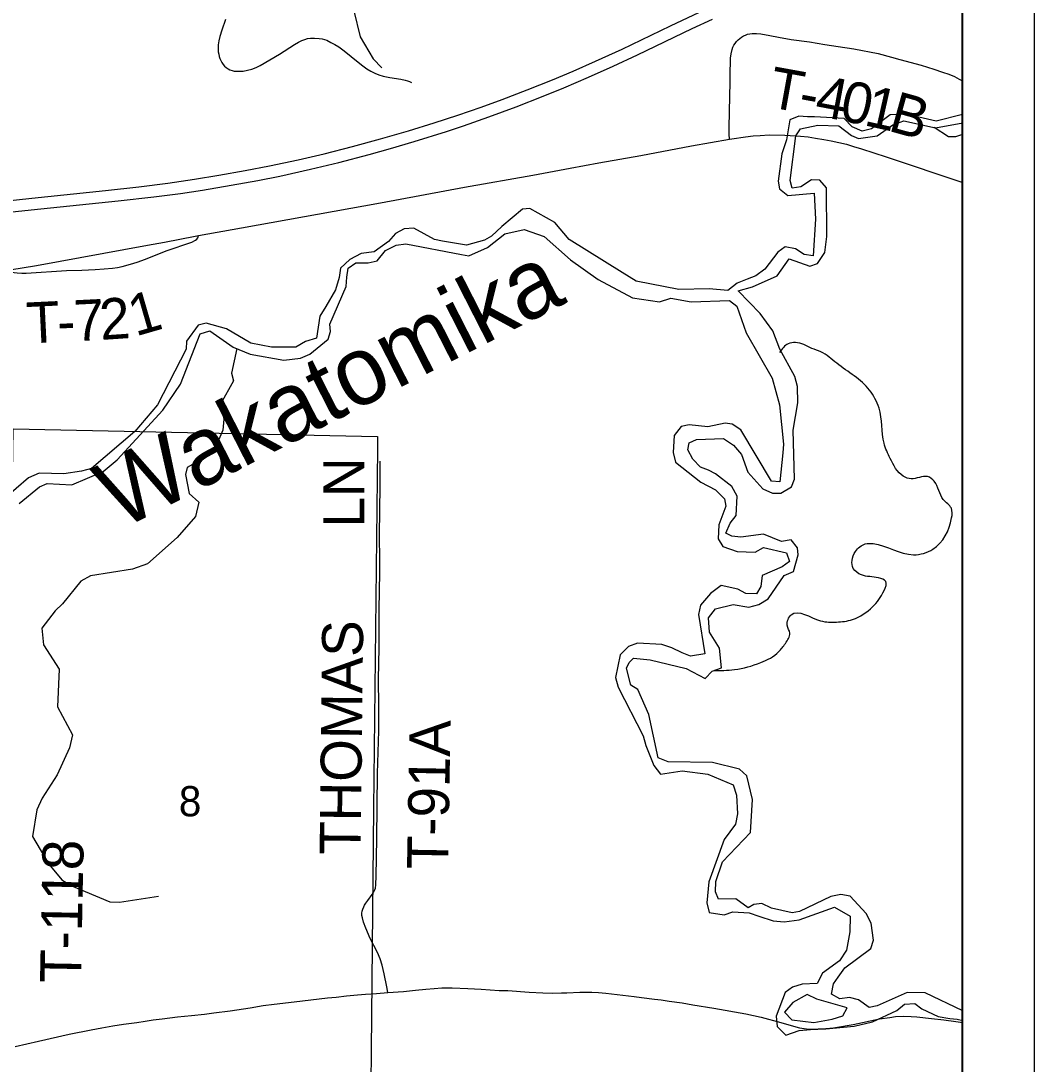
# Model space of a CAD drawing. Extents: x 0 to 34, y 0 to 22.
# Drawn here: x 8.096 to 9.5, y 19.303 to 20.748 of the extents above; entities that cross this region are included whole.
import ezdxf

# ---------------------------------------------------------------- set-up
doc = ezdxf.new("R2010")
doc.units = 0
for name, color, linetype in [('GM_X_County', 7, 'Continuous'), ('GM_X_County_Road', 7, 'Continuous'), ('GM_X_Minor_River', 7, 'Continuous'), ('GM_X_Minor_River_Text', 7, 'Continuous'), ('GM_X_Section', 7, 'Continuous'), ('GM_X_Section_Text', 7, 'Continuous'), ('GM_X_State_Route', 7, 'Continuous'), ('GM_X_Township', 7, 'Continuous'), ('GM_X_Township_Road', 7, 'Continuous'), ('GM_X_Township_Road_Text', 7, 'Continuous'), ('SH_Data', 7, 'Continuous')]:
    doc.layers.add(name, color=color, linetype=linetype)

msp = doc.modelspace()

# ---------------------------------------------------------------- linework, layer by layer
at = {"layer": 'GM_X_County'}
msp.add_lwpolyline([(7.0736, 21.2003), (2.6013, 21.2003), (2.6013, 14.4003), (9.4013, 14.4003), (9.4013, 21.1598)], dxfattribs=at)
at = {"layer": 'GM_X_County_Road'}
for points in [[(8.3426, 20.4502), (8.402, 20.4611), (8.5947, 20.4955), (8.7107, 20.5171), (8.8055, 20.5338), (8.8575, 20.5435), (8.8971, 20.5509), (8.9552, 20.5614), (9.0255, 20.5744), (9.0778, 20.5836)], [(9.0778, 20.5836), (9.0812, 20.5842), (9.1, 20.587), (9.1107, 20.5884), (9.1203, 20.589), (9.1328, 20.5896), (9.1545, 20.5894), (9.1762, 20.5881), (9.1872, 20.5868), (9.1973, 20.5854), (9.2085, 20.5835), (9.219, 20.5817), (9.2401, 20.5768), (9.2499, 20.5737), (9.2607, 20.5705), (9.295, 20.5593), (9.4013, 20.5238)], [(8.2717, 20.437), (8.2951, 20.4413), (8.3379, 20.4493), (8.3426, 20.4502)], [(8.0813, 20.4027), (8.1179, 20.4089), (8.2717, 20.437)], [(8.6046, 19.4017), (8.6266, 19.4034), (8.6432, 19.4049), (8.6574, 19.4063), (8.669, 19.4076), (8.6793, 19.4084), (8.6939, 19.4085), (8.7155, 19.4074), (8.7341, 19.4063), (8.7587, 19.4048), (8.7708, 19.4044), (8.8006, 19.4023), (8.8192, 19.4014), (8.8329, 19.4011), (8.8452, 19.4014), (8.8527, 19.4014), (8.8708, 19.4023), (8.8872, 19.4023), (8.8965, 19.402), (8.9067, 19.401), (8.946, 19.3962), (8.9559, 19.3949), (8.9741, 19.3926), (8.9832, 19.3915), (8.9945, 19.3899), (9.0123, 19.3874), (9.0274, 19.3847), (9.0561, 19.3801), (9.1006, 19.3724), (9.1218, 19.3675), (9.1489, 19.3601), (9.1698, 19.3544), (9.1751, 19.3531), (9.1784, 19.3524), (9.1845, 19.3517), (9.1942, 19.3512), (9.2003, 19.3512), (9.2065, 19.3514), (9.2219, 19.353), (9.2494, 19.3577), (9.2858, 19.3653), (9.3002, 19.3674), (9.3078, 19.3684), (9.3192, 19.3693), (9.3296, 19.3687), (9.3376, 19.368), (9.3579, 19.366), (9.3749, 19.3639), (9.3916, 19.3617), (9.4013, 19.3603)], [(8.0885, 19.3272), (8.1209, 19.3346), (8.1634, 19.344), (8.1938, 19.35), (8.2087, 19.3528), (8.2236, 19.3556), (8.2386, 19.358), (8.2568, 19.3604), (8.2686, 19.3622), (8.2794, 19.3641), (8.2919, 19.3656), (8.3134, 19.368), (8.3326, 19.3698), (8.3506, 19.3718), (8.3638, 19.3735), (8.3864, 19.3765), (8.414, 19.3808), (8.4322, 19.3837), (8.4474, 19.3858), (8.4751, 19.389), (8.5209, 19.3943), (8.5331, 19.3956), (8.5473, 19.3971), (8.5625, 19.3984), (8.5738, 19.3994), (8.5892, 19.4003), (8.6046, 19.4017)]]:
    msp.add_lwpolyline(points, dxfattribs=at)
at = {"layer": 'GM_X_Minor_River'}
for points in [[(8.4113, 21.1729), (8.4074, 21.1403), (8.3955, 21.1084), (8.397, 21.0936), (8.4138, 21.0694), (8.4237, 21.046), (8.4228, 21.0099), (8.4233, 20.9773), (8.4287, 20.9473), (8.4631, 20.8811), (8.4939, 20.8353), (8.5133, 20.8077), (8.5517, 20.7718), (8.5578, 20.7616), (8.5663, 20.7255), (8.5842, 20.6949), (8.5964, 20.6828)], [(9.2479, 20.6009), (9.2368, 20.6126), (9.1959, 20.6147), (9.1861, 20.6147), (9.174, 20.6158), (9.1615, 20.6104), (9.1571, 20.5827), (9.1507, 20.5637), (9.1456, 20.5254), (9.1472, 20.5152), (9.1586, 20.5057), (9.1953, 20.5088), (9.1972, 20.473), (9.1941, 20.4224), (9.1816, 20.4239), (9.1695, 20.4318), (9.1551, 20.4348), (9.1449, 20.4275), (9.1268, 20.4036), (9.1144, 20.3944), (9.1023, 20.3898), (9.0887, 20.3845), (9.0755, 20.3742), (9.0497, 20.3767), (9.0077, 20.3754), (8.9486, 20.387), (8.9292, 20.3991), (8.856, 20.4447), (8.8362, 20.4682), (8.8013, 20.4878), (8.7911, 20.487), (8.7624, 20.463), (8.7484, 20.4493), (8.7386, 20.4439), (8.7139, 20.4372), (8.6803, 20.4426), (8.6694, 20.4448), (8.6405, 20.4603), (8.6273, 20.4595), (8.6152, 20.453), (8.6054, 20.4419), (8.5857, 20.4278), (8.5676, 20.4255), (8.5521, 20.4171), (8.5393, 20.4053), (8.5371, 20.392), (8.532, 20.375), (8.5187, 20.3521), (8.5104, 20.3388), (8.5057, 20.3081), (8.4906, 20.3034), (8.4774, 20.2959), (8.4435, 20.2959), (8.4148, 20.3013), (8.3814, 20.3212), (8.353, 20.3291), (8.3421, 20.326), (8.3259, 20.304), (8.3252, 20.293), (8.2857, 20.2158), (8.2541, 20.1789), (8.1941, 20.1278), (8.1802, 20.124), (8.156, 20.1201), (8.1219, 20.1211), (8.1071, 20.1146), (8.0728, 20.0853)], [(9.0539, 19.8471), (9.0671, 19.8517), (9.0643, 19.8787), (9.0502, 19.901), (9.049, 19.9207), (9.0588, 19.9333), (9.083, 19.9391), (9.1046, 19.9357), (9.1186, 19.9392), (9.1314, 19.9472), (9.1536, 19.9795), (9.1668, 19.9852), (9.1732, 20.008), (9.172, 20.0179), (9.1636, 20.0289), (9.15, 20.0265), (9.1249, 20.0366), (9.0938, 20.0324), (9.0812, 20.0338), (9.0731, 20.038), (9.0787, 20.0521), (9.0874, 20.0627), (9.0888, 20.0893), (9.0812, 20.1026), (9.0588, 20.1203), (9.0489, 20.1252), (9.0379, 20.1293), (9.0272, 20.1407), (9.0204, 20.1536), (9.0219, 20.1631), (9.0321, 20.168), (9.0699, 20.1693), (9.0836, 20.1599), (9.0946, 20.147), (9.1034, 20.1227), (9.124, 20.0997), (9.1376, 20.0933), (9.149, 20.0937), (9.1637, 20.1021), (9.1682, 20.1127), (9.166, 20.1806), (9.1727, 20.2186), (9.1722, 20.241), (9.1687, 20.255), (9.1477, 20.2929), (9.1378, 20.3182), (9.1203, 20.3425), (9.0898, 20.3738), (9.1099, 20.3792), (9.1439, 20.3945), (9.1608, 20.4181), (9.1893, 20.4079), (9.1998, 20.4114), (9.21, 20.427), (9.2129, 20.449), (9.2123, 20.5165), (9.2031, 20.5271), (9.1914, 20.5275), (9.177, 20.5179), (9.1646, 20.516), (9.1619, 20.5266), (9.1699, 20.5885), (9.1763, 20.598), (9.2005, 20.603), (9.2293, 20.6023), (9.2468, 20.5891), (9.2566, 20.5846), (9.2827, 20.5885), (9.3042, 20.6037), (9.3194, 20.6091), (9.3633, 20.5997), (9.4013, 20.6062)], [(9.4013, 20.6184), (9.4007, 20.6181), (9.3644, 20.6085), (9.3224, 20.6186), (9.3004, 20.6174), (9.2747, 20.5983), (9.2619, 20.5948), (9.2479, 20.6009)], [(9.3613, 20.6002), (9.3815, 20.5877), (9.3914, 20.5873), (9.4013, 20.5906)], [(8.0941, 20.0793), (8.122, 20.1022), (8.1329, 20.1068), (8.167, 20.105), (8.2104, 20.1234), (8.2297, 20.1397), (8.293, 20.2086), (8.3174, 20.2444), (8.3448, 20.3143), (8.358, 20.3185), (8.3903, 20.2959), (8.4141, 20.2861), (8.4607, 20.2775), (8.4838, 20.2803), (8.4967, 20.286), (8.5219, 20.3066), (8.5253, 20.3176), (8.5245, 20.3275), (8.547, 20.3795), (8.5481, 20.3928), (8.5499, 20.4053), (8.5603, 20.4127), (8.5773, 20.4127), (8.59, 20.4153), (8.6013, 20.4298), (8.6164, 20.437), (8.6296, 20.4386), (8.7069, 20.4241), (8.7168, 20.4222), (8.7428, 20.4337), (8.767, 20.4527), (8.7935, 20.4585), (8.8211, 20.4488), (8.8576, 20.4167), (8.896, 20.3895), (8.9434, 20.3638), (8.9809, 20.3587), (8.9968, 20.3636), (9.0248, 20.3584), (9.0778, 20.3605), (9.088, 20.3526), (9.1011, 20.3155), (9.1369, 20.2526), (9.1473, 20.2158), (9.1528, 20.1612), (9.1518, 20.1495), (9.1478, 20.1092), (9.136, 20.11), (9.0937, 20.1811), (9.0816, 20.1891), (9.0721, 20.1905), (9.0479, 20.1855), (9.0221, 20.1881), (9.0112, 20.1858), (9.0014, 20.1732), (9, 20.1497), (9.003, 20.1364), (9.0384, 20.1085), (9.0585, 20.0983), (9.071, 20.0855), (9.073, 20.0756), (9.0632, 20.0494), (9.0622, 20.03), (9.0687, 20.0194), (9.0887, 20.0127), (9.1134, 20.0116), (9.1251, 20.0181), (9.1569, 20.011), (9.1611, 19.9989), (9.1509, 19.9913), (9.1233, 19.9794), (9.1215, 19.9642), (9.1155, 19.954), (9.1004, 19.9547), (9.0897, 19.9603), (9.0666, 19.9656), (9.0519, 19.9545), (9.038, 19.9385), (9.035, 19.9252)], [(8.3955, 20.2937), (8.3881, 20.2596), (8.3908, 20.249), (8.3731, 20.2166), (8.3774, 20.1962), (8.3763, 20.1806), (8.3666, 20.1582), (8.3439, 20.1387), (8.3269, 20.1288), (8.3243, 20.1193), (8.3293, 20.0928), (8.343, 20.0811), (8.3382, 20.0613), (8.3129, 20.032), (8.2718, 19.9954), (8.251, 19.9881), (8.1927, 19.9791), (8.1794, 19.9718), (8.1542, 19.9402), (8.144, 19.9307), (8.1255, 19.9063), (8.1279, 19.8836), (8.1493, 19.8495), (8.1473, 19.7975), (8.1679, 19.7589), (8.1638, 19.7407), (8.1466, 19.7035), (8.1259, 19.6711), (8.1187, 19.6548), (8.1125, 19.618), (8.135, 19.5797), (8.1533, 19.5578), (8.1658, 19.5499), (8.2194, 19.5274), (8.233, 19.5271), (8.2868, 19.5353)], [(9.035, 19.9252), (9.0436, 19.871), (9.0239, 19.8679), (9.0125, 19.8724), (8.9981, 19.8792), (8.9844, 19.8837), (8.9504, 19.8859), (8.9379, 19.8809), (8.9266, 19.8695), (8.9203, 19.8383), (8.9238, 19.8247), (8.9585, 19.7573), (8.9623, 19.744), (8.9734, 19.7164), (8.9822, 19.7042), (9.0124, 19.7089), (9.0481, 19.7041), (9.0833, 19.6894), (9.0879, 19.6754), (9.0892, 19.6492), (9.0862, 19.6348), (9.0708, 19.6139), (9.0495, 19.555), (9.0465, 19.5262), (9.05, 19.5125), (9.0705, 19.5096), (9.0826, 19.5138), (9.1053, 19.5123), (9.1186, 19.5074), (9.1383, 19.5011), (9.1538, 19.4996), (9.1746, 19.5027), (9.2234, 19.5199), (9.245, 19.5075), (9.2447, 19.4859), (9.2399, 19.4604), (9.2305, 19.4456), (9.2067, 19.4288), (9.1996, 19.4144), (9.1788, 19.4136), (9.1652, 19.4093), (9.155, 19.4017), (9.1426, 19.3691), (9.1442, 19.3546), (9.156, 19.3429), (9.1745, 19.3491), (9.201, 19.3514), (9.2116, 19.3515), (9.2509, 19.3554), (9.2763, 19.3612), (9.3099, 19.3768), (9.3205, 19.3856), (9.3348, 19.3868), (9.3443, 19.3792), (9.3671, 19.3687), (9.383, 19.3657), (9.3932, 19.365), (9.4013, 19.3633)], [(9.4013, 19.3763), (9.3492, 19.4012), (9.3242, 19.4019), (9.2826, 19.3832), (9.2713, 19.3813), (9.2568, 19.3918), (9.2443, 19.3948), (9.2307, 19.3933), (9.2193, 19.3997), (9.2219, 19.4137), (9.2283, 19.4232), (9.2377, 19.4361), (9.274, 19.4628), (9.2777, 19.4742), (9.2742, 19.4977), (9.2673, 19.5114), (9.2452, 19.5352), (9.2324, 19.5374), (9.2184, 19.5347), (9.1749, 19.5141), (9.1647, 19.5122), (9.1363, 19.5185), (9.1226, 19.5249), (9.1117, 19.5237), (9.1037, 19.5191), (9.0867, 19.5318), (9.0628, 19.5312), (9.0586, 19.5414), (9.0589, 19.5558), (9.0683, 19.5828), (9.1071, 19.6235), (9.1099, 19.669), (9.1022, 19.702), (9.0919, 19.7111), (9.0544, 19.7204), (8.9931, 19.7214), (8.9794, 19.727), (8.9663, 19.7869), (8.951, 19.8217), (8.9415, 19.8274), (8.9352, 19.8513), (8.939, 19.8588), (8.9448, 19.865), (8.9679, 19.8624), (9.0179, 19.8508), (9.0441, 19.8369), (9.0539, 19.8471)], [(9.1989, 19.3924), (9.1856, 19.3992), (9.1656, 19.3881), (9.1543, 19.3748), (9.1642, 19.3642), (9.1949, 19.3605), (9.2202, 19.3648)], [(9.2202, 19.3648), (9.235, 19.3694), (9.241, 19.3804), (9.1989, 19.3924)]]:
    msp.add_lwpolyline(points, dxfattribs=at)
for points in [[(9.0552, 19.8476), (9.0849, 19.8491), (9.1212, 19.8588), (9.1461, 19.8736), (9.1555, 19.8854), (9.1615, 19.8995), (9.1581, 19.9105), (9.1633, 19.9249), (9.2042, 19.9167), (9.2262, 19.9149), (9.2485, 19.9184), (9.2761, 19.9359), (9.2923, 19.9587), (9.2945, 19.9713), (9.2846, 19.9762), (9.2607, 19.9803), (9.2494, 19.9893), (9.2478, 20.0003), (9.2527, 20.0129), (9.2659, 20.0231), (9.2768, 20.0236), (9.3329, 20.0082), (9.3598, 20.0159), (9.3857, 20.0592), (9.3853, 20.0725), (9.3742, 20.0846), (9.3616, 20.11), (9.3522, 20.1164), (9.3295, 20.1133), (9.3188, 20.117), (9.3006, 20.1416), (9.2921, 20.1625), (9.2851, 20.2114), (9.2794, 20.2246), (9.2721, 20.236), (9.2266, 20.2734), (9.2045, 20.2893), (9.192, 20.2938)], [(9.192, 20.2938), (9.1693, 20.302), (9.1594, 20.3005), (9.1474, 20.2883)]]:
    msp.add_spline(points, degree=3, dxfattribs=at)
at = {"layer": 'GM_X_Section'}
msp.add_lwpolyline([(8.0858, 20.1828), (8.5906, 20.172), (8.5904, 20.1552), (8.5847, 19.6569), (8.5803, 19.1784), (8.0709, 19.1994)], close=True, dxfattribs=at)
at = {"layer": 'GM_X_State_Route'}
for points in [[(8.0559, 20.4963), (8.1115, 20.5023), (8.2135, 20.5128), (8.2598, 20.5178), (8.2999, 20.5229), (8.3368, 20.5283), (8.3706, 20.5337), (8.4073, 20.5403), (8.4408, 20.5468), (8.4803, 20.5552), (8.5166, 20.5637), (8.5557, 20.5737), (8.5947, 20.5842), (8.6335, 20.5954), (8.6691, 20.6063), (8.7017, 20.6169), (8.734, 20.628), (8.7632, 20.6387), (8.7979, 20.6521), (8.8326, 20.6658), (8.8613, 20.6778), (8.8926, 20.6916), (8.9292, 20.7086), (8.9964, 20.7408), (9.0442, 20.7633)], [(8.0581, 20.4803), (8.1106, 20.4859), (8.2311, 20.4984), (8.2805, 20.5039), (8.3174, 20.5087), (8.3481, 20.5132), (8.3879, 20.5199), (8.4246, 20.5266), (8.455, 20.5327), (8.4974, 20.5423), (8.5366, 20.5516), (8.5787, 20.5626), (8.6086, 20.5708), (8.6413, 20.5805), (8.6858, 20.5944), (8.7093, 20.6022), (8.7445, 20.6146), (8.7823, 20.6287), (8.8199, 20.6433), (8.8487, 20.655), (8.8829, 20.6697), (8.917, 20.6848), (8.9507, 20.7005), (9.0263, 20.7369), (9.0545, 20.7498)]]:
    msp.add_lwpolyline(points, dxfattribs=at)
at = {"layer": 'GM_X_Township'}
msp.add_line((9.4013, 16.1226), (9.4013, 21.1598), dxfattribs=at)
at = {"layer": 'GM_X_Township_Road'}
for points in [[(8.38, 20.7496), (8.3749, 20.7349), (8.3721, 20.7261), (8.3707, 20.72), (8.3697, 20.7144), (8.3696, 20.7108), (8.3696, 20.7077), (8.3699, 20.7046), (8.3704, 20.7015), (8.3711, 20.6985), (8.3721, 20.6955), (8.3732, 20.6927), (8.3747, 20.6899), (8.3764, 20.6873), (8.3784, 20.685), (8.3807, 20.6829), (8.3833, 20.6812), (8.386, 20.6799), (8.389, 20.6789), (8.392, 20.6782), (8.3951, 20.6779), (8.3982, 20.6778), (8.4044, 20.6781), (8.4105, 20.6792), (8.4165, 20.6808), (8.4223, 20.683), (8.4279, 20.6857), (8.4414, 20.6935), (8.4545, 20.7017), (8.4756, 20.7149), (8.481, 20.718), (8.4855, 20.7203), (8.4896, 20.7219), (8.4933, 20.723), (8.4974, 20.7236), (8.5032, 20.7236), (8.5095, 20.7233), (8.5137, 20.7227), (8.5201, 20.7211), (8.5259, 20.7179), (8.5313, 20.715), (8.5366, 20.7117), (8.5441, 20.7062), (8.5539, 20.6985), (8.5682, 20.6867), (8.5757, 20.6812), (8.581, 20.6779), (8.5865, 20.675), (8.5923, 20.6727), (8.5982, 20.671), (8.6074, 20.6693), (8.6227, 20.6669), (8.6288, 20.6656), (8.6318, 20.6647), (8.6347, 20.6636), (8.6374, 20.6623)], [(9.0778, 20.5836), (9.0777, 20.5907), (9.0777, 20.6), (9.0781, 20.6218), (9.0785, 20.6435), (9.0787, 20.6621), (9.079, 20.6776), (9.0792, 20.69), (9.0796, 20.6962), (9.0805, 20.7022), (9.0817, 20.7082), (9.0828, 20.7111), (9.0842, 20.7139), (9.0858, 20.7165), (9.0878, 20.7189), (9.0899, 20.7212), (9.0922, 20.7233), (9.0947, 20.7251), (9.0974, 20.7267), (9.1002, 20.728), (9.1031, 20.729), (9.1061, 20.7297), (9.1092, 20.7301), (9.1123, 20.7302), (9.1154, 20.7301), (9.1216, 20.7295), (9.1339, 20.7276), (9.1461, 20.7253), (9.1633, 20.7219), (9.1888, 20.7184), (9.2102, 20.715), (9.2286, 20.712), (9.2501, 20.7088), (9.284, 20.7023), (9.3025, 20.6975), (9.3138, 20.6943), (9.3434, 20.6864), (9.3523, 20.6835), (9.3611, 20.6806), (9.3729, 20.6767), (9.3817, 20.6736), (9.3897, 20.6707), (9.3961, 20.6671), (9.4013, 20.6642)], [(8.0813, 20.4027), (8.0832, 20.4005), (8.085, 20.3994), (8.0873, 20.3989), (8.0912, 20.3985), (8.0976, 20.3981), (8.1038, 20.3983), (8.1594, 20.4019), (8.181, 20.4025), (8.1995, 20.4033), (8.2119, 20.4042), (8.2233, 20.4052), (8.2301, 20.4061), (8.2365, 20.4073), (8.2484, 20.4106), (8.2573, 20.4133), (8.2689, 20.4175), (8.2975, 20.429), (8.333, 20.4413), (8.3385, 20.4439), (8.34, 20.4452), (8.3413, 20.447), (8.3426, 20.4502)], [(8.6046, 19.4017), (8.6032, 19.4097), (8.5996, 19.4276), (8.5968, 19.4397), (8.5939, 19.4486), (8.5902, 19.4571), (8.5804, 19.4765), (8.5743, 19.4908), (8.5711, 19.4995), (8.5694, 19.5055), (8.5689, 19.5085), (8.5689, 19.5116), (8.5693, 19.5147), (8.57, 19.5175), (8.5713, 19.5205), (8.5725, 19.5229), (8.5744, 19.5256), (8.5768, 19.5292), (8.5828, 19.5374), (8.5841, 19.5394), (8.5852, 19.5411), (8.5865, 19.5439), (8.5874, 19.5463), (8.5878, 19.5478), (8.588, 19.5496), (8.5882, 19.5518), (8.5887, 19.5623), (8.5893, 19.6151), (8.5906, 19.7053), (8.5921, 19.7643), (8.5924, 19.7985), (8.5917, 19.8358), (8.5925, 19.8793), (8.5926, 19.9147), (8.5927, 19.9321), (8.5938, 19.9839), (8.5938, 19.9942), (8.5937, 20.0098), (8.5933, 20.0257), (8.5933, 20.0358), (8.5942, 20.103), (8.5942, 20.1216), (8.5942, 20.1274), (8.5943, 20.1309), (8.594, 20.1378)]]:
    msp.add_lwpolyline(points, dxfattribs=at)
at = {"layer": 'SH_Data'}
for p, q in [((9.5, 21.2997), (9.5, 14.2997)), ((9.4, 21.1997), (9.4, 14.3997))]:
    msp.add_line(p, q, dxfattribs=at)

# ---------------------------------------------------------------- texts
at = {"layer": 'GM_X_Minor_River_Text'}
msp.add_text('Wakatomika', height=0.0947, rotation=27.0325, dxfattribs=at).set_placement((8.2338, 20.0417))
at = {"layer": 'GM_X_Section_Text'}
msp.add_text('8', height=0.0419, rotation=0, dxfattribs=at).set_placement((8.3152, 19.6459))
at = {"layer": 'GM_X_Township_Road_Text'}
for s, height, rotation, p in [('T', 0.0568, 349.6978, (9.1298, 20.6287)), ('4', 0.0568, 349.3014, (9.1945, 20.6169)), ('0', 0.0568, 348.3359, (9.2287, 20.6105)), ('1', 0.0568, 347.303, (9.2627, 20.6035)), ('-', 0.0568, 349.6163, (9.1716, 20.6211)), ('B', 0.0568, 344.4519, (9.2961, 20.5959)), ('7', 0.0568, 2.8512, (8.171, 20.3038)), ('2', 0.0568, 3.8889, (8.2071, 20.3056)), ('1', 0.0568, 16.1648, (8.2551, 20.3103)), ('T', 0.0568, 2.761, (8.1052, 20.3007)), ('-', 0.0568, 2.7792, (8.1477, 20.3027)), ('LN', 0.05682, 90, (8.572, 20.0459)), ('THOMAS', 0.05682, 89.3516, (8.567, 19.5921)), ('T-91A', 0.05682, 88.9695, (8.688, 19.572)), ('T-118', 0.05682, 88.9027, (8.1796, 19.4146))]:
    msp.add_text(s, height=height, rotation=rotation, dxfattribs=at).set_placement(p)

doc.saveas('drawing.dxf')
